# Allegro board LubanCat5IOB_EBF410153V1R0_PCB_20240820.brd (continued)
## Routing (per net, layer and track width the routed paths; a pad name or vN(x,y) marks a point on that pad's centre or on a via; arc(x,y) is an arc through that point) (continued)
PCIE30_PORT0_RX0P: length 157.5
  TOP w0.165: v2(71.42,16.88) 71.69,17.15 71.69,17.91 71.64,17.95 J2.20 ; v1(162.49,87.77) 162.19,88.07 162.19,92.81 162.29,92.91 J19.43
  BOTTOM w0.165: v2(71.42,16.88) 71.66,16.63 71.66,16.09 72.12,15.62 73.37,15.62 73.79,16.04 73.79,18.07 arc(73.93,18.78) 74.33,19.38 74.64,19.69 arc(75.21,20.07) 75.9,20.21 79.45,20.21 arc(79.51,20.21) 79.56,20.22 81.94,20.63 arc(81.99,20.63) 82.05,20.63 84.43,20.22 arc(84.48,20.21) 84.53,20.21 arc(84.59,20.21) 84.64,20.22 86.69,20.57 arc(86.9,20.59) 87.1,20.57 89.15,20.22 arc(89.21,20.21) 89.26,20.21 92.33,20.21 arc(93.22,20.58) 93.59,21.47 93.59,24.46 94.28,28.43 93.6,32.3 93.58,32.59 94.02,35.16 93.49,38.26 94.05,41.49 94.05,41.65 94.04,41.65 94.04,45.73 95.2,48.3 96.24,49.72 98.04,51.53 arc(98.77,52.01) 99.63,52.18 101.33,52.18 105.86,51.4 110.4,52.18 111.18,52.18 114.51,51.61 117.84,52.18 124.02,52.18 arc(124.99,52.38) 125.81,52.92 126.26,53.38 arc(126.99,53.87) 127.85,54.04 132.12,54.04 135.52,53.45 138.92,54.04 144.93,54.04 arc(145.75,54.2) 146.44,54.66 147.04,55.26 arc(147.38,55.77) 147.5,56.37 147.5,59.85 147.48,60.07 146.92,63.28 147.48,66.49 147.5,66.71 147.5,71.47 arc(147.84,73.18) 148.81,74.63 152.55,78.37 152.62,78.44 arc(152.95,78.94) 153.07,79.54 arc(153.18,80.1) 153.5,80.57 153.66,80.72 157.67,84.74 157.78,84.85 arc(158.48,85.32) 159.31,85.48 159.92,85.48 arc(160.64,85.63) 161.25,86.03 162.19,86.97 162.19,87.47 v1(162.49,87.77)
PCIE30_PORT0_RX1N: length 150.9
  TOP w0.165: v2(73,20.37) 72.76,20.13 72.76,19.78 72.84,19.7 J2.26 ; J19.29 158.79,92.91 158.9,92.81 158.9,90.83 arc(158.83,90.68) 158.68,90.62 arc(158.53,90.55) 158.47,90.4 158.47,90.17 arc(158.53,90.02) 158.68,89.95 arc(158.83,89.89) 158.9,89.74 158.9,89.51 arc(158.83,89.36) 158.68,89.29 arc(158.53,89.23) 158.47,89.08 158.47,88.85 arc(158.53,88.7) 158.68,88.63 arc(158.83,88.57) 158.9,88.42 158.9,88.07 v1(158.59,87.77)
  BOTTOM w0.165: v1(158.59,87.77) 158.9,88.07 158.9,88.51 arc(158.72,88.93) 158.3,89.11 156.87,89.11 arc(155.99,88.93) 155.25,88.44 154.97,88.15 150.69,83.87 arc(150.57,83.7) 150.53,83.5 150.53,79.91 arc(150.41,79.3) 150.06,78.78 146.99,75.71 146.99,75.7 arc(146.03,74.27) 145.69,72.58 145.69,71.68 arc(145.48,70.6) 144.86,69.68 144.1,68.92 arc(143.85,68.54) 143.76,68.1 143.76,67.44 144.27,66.93 144.27,62.91 arc(144.27,62.85) 144.26,62.8 143.79,60.11 arc(143.79,60.05) 143.79,59.99 143.8,59.99 143.8,59.08 143.79,59.07 143.79,57.12 arc(143.36,56.09) 142.33,55.66 138.78,55.66 135.52,55.1 132.26,55.66 122.72,55.66 arc(122.13,55.55) 121.64,55.21 121.29,54.87 arc(120.61,54.41) 119.8,54.25 114.68,54.25 arc(114.39,54.31) 114.15,54.47 arc(113.63,54.82) 113.01,54.94 109.68,54.94 105.56,54.23 102.1,54.83 99.27,54.83 arc(97.76,54.53) 96.48,53.67 94.46,51.65 93.7,50.36 93.17,49.6 92.52,47.77 92.11,46.29 92.11,42.02 92.08,41.39 91.52,38.15 92.03,35.21 91.56,32.51 92.18,28.93 91.95,27.58 91.85,26.37 arc(91.57,24.97) 90.78,23.78 89.38,22.39 arc(88.62,21.88) 87.72,21.7 86.3,21.7 arc(86.21,21.71) 86.11,21.7 84.44,21.41 arc(84.38,21.4) 84.33,21.4 arc(84.2,21.41) 84.07,21.42 81.92,21.8 arc(81.87,21.8) 81.81,21.8 79.66,21.42 arc(79.61,21.42) 79.55,21.42 79.25,21.42 arc(79.2,21.42) 79.14,21.42 76.82,21.83 arc(76.76,21.83) 76.71,21.83 74.38,21.42 arc(74.33,21.42) 74.28,21.42 72.96,21.42 72.76,21.21 72.76,20.62 v2(73,20.37)
PCIE30_PORT0_RX1P: length 150.8
  TOP w0.165: v2(72.23,20.37) 72.47,20.13 72.47,19.73 72.44,19.7 J2.24 ; v1(159.49,87.77) 159.19,88.07 159.19,92.81 159.29,92.91 J19.31
  BOTTOM w0.165: v1(159.49,87.77) 159.19,88.07 159.19,88.51 arc(158.93,89.14) 158.3,89.4 156.87,89.4 arc(155.88,89.2) 155.04,88.64 154.76,88.36 150.48,84.08 arc(150.3,83.82) 150.24,83.5 150.24,79.91 arc(150.14,79.41) 149.86,78.99 146.78,75.91 arc(145.76,74.38) 145.4,72.58 145.4,71.68 arc(145.21,70.71) 144.66,69.89 143.9,69.12 arc(143.58,68.65) 143.47,68.1 143.47,67.31 143.98,66.81 143.98,62.91 arc(143.98,62.88) 143.98,62.85 143.51,60.16 arc(143.5,60.05) 143.51,59.94 143.5,59.93 143.5,57.12 arc(143.16,56.3) 142.33,55.96 138.76,55.96 135.52,55.39 132.28,55.96 122.72,55.96 arc(122.02,55.82) 121.43,55.42 121.09,55.08 arc(120.5,54.68) 119.8,54.55 114.68,54.55 arc(114.5,54.58) 114.35,54.68 arc(113.74,55.09) 113.01,55.23 109.66,55.23 105.56,54.52 102.12,55.12 99.27,55.12 arc(97.65,54.8) 96.28,53.88 94.23,51.83 94.2,51.79 93.45,50.52 92.91,49.73 92.24,47.86 91.82,46.33 91.82,42.03 91.79,41.4 91.23,38.15 91.73,35.21 91.27,32.51 91.89,28.93 91.66,27.62 91.55,26.38 91.55,26.37 arc(91.3,25.08) 90.57,23.99 89.18,22.6 arc(88.51,22.15) 87.72,21.99 86.33,21.99 arc(86.2,22) 86.06,21.99 84.39,21.7 arc(84.36,21.7) 84.33,21.69 arc(84.23,21.7) 84.12,21.71 81.97,22.09 arc(81.87,22.09) 81.76,22.09 79.61,21.71 arc(79.58,21.71) 79.55,21.71 79.25,21.71 arc(79.22,21.71) 79.19,21.71 76.87,22.12 arc(76.76,22.12) 76.66,22.12 74.33,21.71 arc(74.31,21.71) 74.28,21.71 72.84,21.71 72.47,21.34 72.47,20.62 v2(72.23,20.37)
PCIE30_PORT0_TX0N: length 151.3
  TOP w0.165: J2.38 75.24,17.95 75.18,17.89 75.18,17.09 v2(75.4,16.88)
  BOTTOM w0.165: v2(75.4,16.88) 75.15,16.63 75.15,16.17 75.32,16 75.9,16 76.09,16.19 76.09,18.15 arc(76.4,18.91) 77.17,19.23 78.52,19.23 arc(78.62,19.27) 78.67,19.38 arc(78.71,19.48) 78.81,19.52 79.18,19.52 arc(79.29,19.48) 79.33,19.38 arc(79.37,19.27) 79.47,19.23 79.84,19.23 arc(79.95,19.27) 79.99,19.38 arc(80.03,19.48) 80.13,19.52 80.5,19.52 arc(80.61,19.48) 80.65,19.38 arc(80.69,19.27) 80.79,19.23 81.16,19.23 arc(81.27,19.27) 81.31,19.38 arc(81.35,19.48) 81.46,19.52 81.82,19.52 arc(81.93,19.48) 81.97,19.38 arc(82.01,19.27) 82.12,19.23 85,19.23 arc(85.03,19.23) 85.06,19.23 86.97,19.57 arc(87.08,19.58) 87.19,19.57 89.1,19.23 arc(89.13,19.23) 89.16,19.23 93.01,19.23 arc(93.83,19.57) 94.17,20.39 94.17,23.86 arc(94.17,23.92) 94.18,23.97 94.69,26.91 arc(94.84,28.67) 94.69,30.42 94.31,32.61 94.71,34.76 94.62,35.28 94.18,37.83 arc(94.17,37.88) 94.17,37.94 arc(94.17,37.99) 94.18,38.04 94.7,41.03 arc(94.7,41.09) 94.7,41.15 94.69,41.17 94.69,44.71 95.61,46.97 98.35,49.7 arc(99.4,50.4) 100.64,50.65 105.86,50.65 110.46,51.45 111.12,51.45 114.51,50.86 117.9,51.45 124.49,51.45 arc(125.58,51.67) 126.51,52.29 126.92,52.69 arc(127.77,53.27) 128.78,53.47 132.07,53.47 135.52,52.87 138.97,53.47 145.67,53.47 arc(146.24,53.58) 146.72,53.9 147.36,54.54 147.49,54.67 arc(147.88,55.26) 148.02,55.95 148.02,59.88 148,60.14 147.45,63.28 148,66.42 148.02,66.68 148.02,70.47 arc(148.42,72.51) 149.58,74.24 151.94,76.6 152.19,76.85 arc(153.06,77.43) 154.08,77.63 154.36,77.63 arc(155.14,77.79) 155.8,78.23 156.64,79.07 arc(157.41,79.59) 158.32,79.77 158.57,79.77 arc(159.01,79.86) 159.38,80.1 159.83,80.55 arc(159.98,80.78) 160.03,81.05 160.03,82.69 arc(160.22,83.63) 160.75,84.42 162.97,86.65 arc(163.31,87.15) 163.43,87.75 163.43,89.45 C177.1
PCIE30_PORT0_TX0P: length 151.3
  TOP w0.165: v2(74.62,16.88) 74.89,17.15 74.89,17.91 74.84,17.95 J2.36
  BOTTOM w0.165: C178.1 163.72,89.45 163.72,87.75 arc(163.58,87.04) 163.18,86.44 161.06,84.32 160.96,84.21 arc(160.49,83.52) 160.32,82.69 160.32,81.05 arc(160.25,80.67) 160.03,80.34 159.59,79.9 arc(159.12,79.59) 158.57,79.48 158.32,79.48 arc(157.52,79.32) 156.84,78.86 156,78.02 arc(155.25,77.52) 154.36,77.34 154.08,77.34 arc(153.17,77.16) 152.4,76.65 152.15,76.39 149.78,74.03 arc(148.69,72.4) 148.31,70.47 148.31,66.67 148.29,66.38 147.75,63.28 148.29,60.18 148.31,59.89 148.31,55.95 arc(148.15,55.14) 147.7,54.47 147.56,54.33 146.93,53.69 arc(146.35,53.31) 145.67,53.17 139,53.17 135.52,52.57 132.04,53.17 128.84,53.17 arc(127.89,52.98) 127.08,52.45 126.72,52.08 arc(125.69,51.4) 124.49,51.16 117.93,51.16 114.51,50.56 111.09,51.16 110.49,51.16 105.89,50.36 100.64,50.36 arc(99.51,50.13) 98.55,49.49 95.86,46.8 94.99,44.66 94.99,41.2 arc(95,41.09) 94.99,40.98 94.47,37.99 arc(94.46,37.97) 94.46,37.94 arc(94.46,37.91) 94.47,37.88 95.01,34.75 94.61,32.61 94.98,30.47 arc(95.13,28.67) 94.98,26.86 94.47,23.92 arc(94.46,23.89) 94.46,23.86 94.46,20.39 arc(94.04,19.36) 93.01,18.94 89.16,18.94 arc(89.1,18.94) 89.05,18.95 87.14,19.28 arc(87.08,19.28) 87.02,19.28 85.11,18.95 arc(85.06,18.94) 85,18.94 77.17,18.94 arc(76.61,18.71) 76.38,18.15 76.38,16.07 76.02,15.71 75.2,15.71 74.86,16.05 74.86,16.63 v2(74.62,16.88)
PCIE30_PORT0_TX1N: length 146.2
  TOP w0.165: J2.42 76.04,19.7 75.99,19.75 75.99,20.02 76.15,20.18 86.27,20.18 arc(86.37,20.14) 86.41,20.04 arc(86.45,19.94) 86.55,19.9 86.93,19.9 arc(87.03,19.94) 87.07,20.04 arc(87.11,20.14) 87.21,20.18 87.59,20.18 arc(87.69,20.14) 87.73,20.04 arc(87.77,19.94) 87.87,19.9 88.25,19.9 arc(88.35,19.94) 88.39,20.04 arc(88.43,20.14) 88.53,20.18 88.91,20.18 arc(89.01,20.14) 89.05,20.04 arc(89.09,19.94) 89.19,19.9 89.57,19.9 arc(89.67,19.94) 89.71,20.04 arc(89.75,20.14) 89.85,20.18 90.35,20.18 90.93,20.77 90.93,22.33 v1(91.2,22.6)
  BOTTOM w0.165: C175.1 160.38,89.45 160.38,87.57 arc(160.24,87.22) 159.88,87.07 158.12,87.07 arc(157.13,86.87) 156.3,86.32 152.46,82.48 arc(151.92,81.67) 151.73,80.71 151.73,80.18 arc(151.59,79.49) 151.2,78.91 147.65,75.35 arc(146.72,73.97) 146.39,72.33 146.39,66.72 arc(146.39,66.69) 146.39,66.66 145.82,63.39 arc(145.81,63.28) 145.82,63.17 146.39,59.9 arc(146.39,59.87) 146.39,59.84 146.39,57.34 arc(146.27,56.71) 145.91,56.18 145.32,55.59 arc(144.83,55.26) 144.25,55.14 138.83,55.14 135.52,54.57 132.21,55.14 126.88,55.14 arc(126.13,54.99) 125.49,54.56 125.03,54.11 arc(124.42,53.7) 123.69,53.55 113.85,53.55 arc(113.64,53.6) 113.47,53.71 arc(112.99,54.03) 112.43,54.14 110.89,54.14 arc(110.84,54.14) 110.78,54.13 106.7,53.42 arc(106.1,53.37) 105.51,53.42 102.52,53.94 arc(102.47,53.95) 102.42,53.95 100.2,53.95 arc(98.35,53.58) 96.79,52.54 94.58,50.33 93.65,48.93 92.76,45.86 92.76,41.64 92.22,38.49 92.74,35.5 92.22,32.55 92.95,28.37 92.37,25.01 92.37,21.8 91.94,21.38 91.3,21.38 90.93,21.74 90.93,22.33 v1(91.2,22.6)
PCIE30_PORT0_TX1P: length 146.2
  TOP w0.165: v1(90.38,22.6) 90.64,22.33 90.64,20.89 90.23,20.47 76.03,20.47 75.69,20.14 75.69,19.75 75.64,19.7 J2.40
  BOTTOM w0.165: v1(90.38,22.6) 90.64,22.33 90.64,21.62 91.18,21.08 92.06,21.08 92.66,21.68 92.66,24.99 93.25,28.37 92.52,32.55 93.03,35.5 92.51,38.49 93.06,41.61 93.06,45.81 93.92,48.81 94.81,50.14 97,52.33 arc(98.47,53.31) 100.2,53.66 102.42,53.66 arc(102.44,53.66) 102.47,53.65 105.46,53.14 arc(106.1,53.08) 106.75,53.14 110.83,53.85 arc(110.86,53.85) 110.89,53.85 112.43,53.85 arc(112.88,53.76) 113.26,53.51 arc(113.53,53.33) 113.85,53.26 123.69,53.26 arc(124.53,53.43) 125.23,53.9 125.69,54.36 arc(126.24,54.72) 126.88,54.85 132.19,54.85 135.52,54.27 138.85,54.85 144.25,54.85 arc(144.94,54.99) 145.52,55.38 146.12,55.97 arc(146.54,56.6) 146.69,57.34 146.69,59.84 arc(146.68,59.89) 146.68,59.95 146.11,63.22 arc(146.1,63.28) 146.11,63.34 146.68,66.61 arc(146.68,66.66) 146.69,66.72 146.69,72.33 arc(146.99,73.85) 147.85,75.15 151.41,78.7 arc(151.86,79.38) 152.02,80.18 152.02,80.71 arc(152.19,81.56) 152.67,82.27 156.51,86.11 arc(157.24,86.6) 158.12,86.78 159.88,86.78 arc(160.44,87.01) 160.67,87.57 160.67,89.45 C176.1
PCIE30_PORT1_REF_CLKN: length 52.1
  TOP w0.114: J2.55 78.84,22.26 78.76,22.34 78.76,23.06 78.35,23.47 78.35,23.79 arc(78.39,23.89) 78.49,23.94 arc(78.6,23.98) 78.64,24.08 78.64,24.25 arc(78.6,24.35) 78.49,24.39 arc(78.39,24.44) 78.35,24.54 78.35,24.71 arc(78.39,24.81) 78.49,24.85 arc(78.6,24.89) 78.64,25 78.64,25.16 arc(78.6,25.27) 78.49,25.31 arc(78.39,25.35) 78.35,25.46 78.35,25.62 arc(78.39,25.72) 78.49,25.77 arc(78.6,25.81) 78.64,25.91 78.64,26.08 arc(78.6,26.18) 78.49,26.22 arc(78.39,26.27) 78.35,26.37 78.35,27.37 77.99,27.72 77.99,30.9 78.5,31.41 78.5,45.87 79.08,46.46 94.44,46.46 98.27,50.29 100.88,50.29 101.08,50.09 R244.1 101.32,49.78 R243.2
PCIE30_PORT1_REF_CLKP: length 51.4
  TOP w0.114: J2.53 78.44,22.26 78.52,22.34 78.52,22.96 78.11,23.37 78.11,27.27 77.75,27.62 77.75,31 78.26,31.51 78.26,45.97 78.98,46.7 94.34,46.7 98.17,50.54 100.94,50.54 101.08,50.68 R245.1 101.35,50.8 R242.2
PCIE30_PORT1_RX0N: length 90.3
  TOP w0.165: J2.37 75.24,22.35 75.19,22.4 75.19,24.99 73.84,26.34 73.84,32.94 73.34,33.44 72.3,33.44 v1(72.04,33.7)
  ART03 w0.114: J20.A17 6.25,41.04 9.55,41.04 10.16,41.65 14.83,41.65 16.03,42.84 18.11,42.84 18.49,43.22 21.88,43.22 arc(21.91,43.22) 21.95,43.22 23.83,43.55 arc(23.87,43.55) 23.91,43.55 25.78,43.22 arc(25.82,43.22) 25.86,43.22 30.46,43.22 34.01,39.66 36.41,39.66 arc(36.43,39.66) 36.45,39.66 38.65,39.28 arc(38.89,39.26) 39.12,39.28 41.32,39.66 arc(41.34,39.66) 41.36,39.66 arc(41.38,39.66) 41.4,39.66 43.88,39.23 arc(43.96,39.22) 44.04,39.23 46.51,39.66 arc(46.53,39.66) 46.55,39.66 51.12,39.66 53.85,39.19 56.58,39.66 58.51,39.33 60.44,39.66 63.55,39.12 66.66,39.66 71.02,39.66 71.37,39.31 71.37,35.12 71.81,34.68 72.6,34.68 72.95,34.33 72.95,33.7 72.66,33.41 72.33,33.41 v1(72.04,33.7)
PCIE30_PORT1_RX0P: length 90.3
  TOP w0.165: J2.35 74.84,22.35 74.89,22.4 74.89,24.87 73.55,26.22 73.55,32.82 73.22,33.15 72.3,33.15 v1(72.04,32.89)
  ART03 w0.114: v1(72.04,32.89) 72.33,33.18 72.75,33.18 73.18,33.61 73.18,34.43 72.69,34.91 71.91,34.91 71.61,35.22 71.61,39.41 71.12,39.9 66.64,39.9 63.55,39.36 60.44,39.9 58.51,39.56 56.58,39.9 53.85,39.42 51.14,39.9 46.55,39.9 arc(46.51,39.89) 46.47,39.89 44,39.46 arc(43.96,39.46) 43.92,39.46 41.44,39.89 arc(41.4,39.89) 41.36,39.9 arc(41.32,39.89) 41.28,39.89 39.08,39.51 arc(38.89,39.49) 38.69,39.51 36.49,39.89 arc(36.45,39.89) 36.41,39.9 34.11,39.9 30.55,43.45 25.86,43.45 arc(25.84,43.45) 25.82,43.45 23.95,43.78 arc(23.87,43.78) 23.79,43.78 21.91,43.45 arc(21.89,43.45) 21.88,43.45 18.39,43.45 18.01,43.07 15.93,43.07 14.74,41.88 10.06,41.88 9.45,41.27 7.8,41.27 7.57,41.5 7.57,41.92 7.8,42.15 J20.A16
PCIE30_PORT1_RX1N: length 92.6
  TOP w0.165: J2.41 76.04,22.35 75.99,22.4 75.99,25.61 74.79,26.81 74.79,34.37 74.24,34.91 67.85,34.91 v1(67.59,35.18)
  ART03 w0.114: v1(67.59,35.18) 67.88,34.88 68.21,34.88 68.44,35.11 68.44,37.17 67.87,37.73 66.84,37.73 arc(66.82,37.73) 66.8,37.73 63.81,37.21 arc(63.73,37.2) 63.65,37.21 60.66,37.73 arc(60.64,37.73) 60.62,37.73 60.48,37.73 arc(60.47,37.73) 60.45,37.73 58.52,37.4 arc(58.44,37.39) 58.36,37.4 56.43,37.73 arc(56.41,37.73) 56.39,37.73 arc(56.37,37.73) 56.35,37.73 53.74,37.28 arc(53.66,37.27) 53.58,37.28 50.97,37.73 arc(50.95,37.73) 50.93,37.73 arc(50.91,37.73) 50.89,37.73 48.79,37.37 arc(48.71,37.36) 48.63,37.37 46.53,37.73 arc(46.51,37.73) 46.49,37.73 arc(46.47,37.73) 46.45,37.73 44.09,37.32 arc(44.01,37.31) 43.93,37.32 41.57,37.73 arc(41.55,37.73) 41.53,37.73 arc(41.51,37.73) 41.49,37.73 39.07,37.31 arc(38.99,37.3) 38.91,37.31 36.49,37.73 arc(36.47,37.73) 36.45,37.73 32.97,37.73 29.52,41.19 26.05,41.19 arc(26.01,41.19) 25.98,41.19 23.91,41.55 arc(23.88,41.55) 23.84,41.55 21.78,41.19 arc(21.74,41.19) 21.7,41.19 16.71,41.19 15.62,40.09 14.12,40.09 13.92,39.89 13.92,37.18 13.56,36.82 9.35,36.82 8.91,37.25 7.55,37.25 7.32,37.02 7.32,36.38 7.55,36.15 J20.A22
PCIE30_PORT1_RX1P: length 92.5
  TOP w0.165: J2.39 75.64,22.35 75.69,22.4 75.69,25.49 74.5,26.68 74.5,34.25 74.12,34.62 67.85,34.62 v1(67.59,34.36)
  ART03 w0.114: v1(67.59,34.36) 67.88,34.65 68.3,34.65 68.67,35.02 68.67,37.27 67.97,37.97 66.84,37.97 arc(66.8,37.96) 66.76,37.96 63.77,37.44 arc(63.73,37.44) 63.69,37.44 60.7,37.96 arc(60.66,37.96) 60.62,37.97 60.48,37.97 arc(60.45,37.96) 60.41,37.96 58.48,37.62 arc(58.44,37.62) 58.4,37.62 56.47,37.96 arc(56.43,37.96) 56.39,37.97 arc(56.35,37.96) 56.31,37.96 53.7,37.5 arc(53.66,37.5) 53.62,37.5 51.01,37.96 arc(50.97,37.96) 50.93,37.97 arc(50.89,37.96) 50.85,37.96 48.75,37.59 arc(48.71,37.59) 48.67,37.59 46.57,37.96 arc(46.53,37.96) 46.49,37.97 arc(46.45,37.96) 46.41,37.96 44.05,37.55 arc(44.01,37.55) 43.97,37.55 41.61,37.96 arc(41.57,37.96) 41.53,37.97 arc(41.49,37.96) 41.45,37.96 39.03,37.54 arc(38.99,37.53) 38.95,37.54 36.53,37.96 arc(36.49,37.96) 36.45,37.97 33.07,37.97 29.62,41.42 26.05,41.42 arc(26.03,41.42) 26.01,41.42 23.95,41.78 arc(23.88,41.78) 23.8,41.78 21.74,41.42 arc(21.72,41.42) 21.7,41.42 16.61,41.42 15.52,40.32 14.03,40.32 13.69,39.99 13.69,37.28 13.46,37.05 9.45,37.05 9.01,37.48 6.47,37.48 J20.A21
PCIE30_PORT1_TX0N: length 89.5
  TOP w0.165: C190.1 v1(12.32,42.54) ; v1(73.99,37.21) 74.25,36.95 75.22,36.95 75.83,36.33 75.83,27.11 76.79,26.16 76.79,22.4 76.84,22.35 J2.45
  ART03 w0.114: v1(73.99,37.21) 73.7,36.92 73.03,36.92 72.8,37.14 72.8,40.17 72.16,40.81 66.56,40.81 63.47,40.27 60.36,40.81 58.51,40.49 56.66,40.81 53.93,40.34 51.22,40.81 46.43,40.81 43.96,40.38 41.46,40.81 38.98,40.38 36.53,40.81 34.77,40.81 31.11,44.46 25.85,44.46 arc(25.83,44.47) 25.81,44.47 23.97,44.79 arc(23.89,44.8) 23.81,44.79 21.97,44.47 arc(21.95,44.47) 21.93,44.46 18.19,44.46 17.76,44.04 13.23,44.04 12.95,44.32 11.33,44.32 10.97,43.95 10.97,43.3 11.33,42.94 11.93,42.94 v1(12.32,42.54)
PCIE30_PORT1_TX0P: length 88.2
  TOP w0.165: v1(73.99,36.39) 74.25,36.65 75.1,36.65 75.54,36.21 75.54,26.99 76.49,26.04 76.49,22.4 76.44,22.35 J2.43 ; C189.1 v1(12.32,43.56)
  ART03 w0.114: v1(73.99,36.39) 73.7,36.68 72.93,36.68 72.57,37.05 72.57,40.08 72.06,40.58 66.58,40.58 63.47,40.04 60.36,40.58 58.51,40.26 56.66,40.58 53.93,40.1 51.2,40.58 46.45,40.58 43.96,40.15 41.46,40.58 38.98,40.15 36.51,40.58 34.67,40.58 31.02,44.23 25.85,44.23 arc(25.81,44.24) 25.77,44.24 23.93,44.56 arc(23.89,44.56) 23.85,44.56 22,44.24 arc(21.97,44.24) 21.93,44.23 18.29,44.23 17.86,43.8 13.13,43.8 12.85,44.08 11.43,44.08 11.2,43.86 11.2,43.4 11.43,43.17 11.93,43.17 v1(12.32,43.56)
PCIE30_PORT1_TX1N: length 90.1
  TOP w0.165: v1(69.88,38.51) 70.14,38.24 76.25,38.24 77.06,37.43 77.06,27.35 77.59,26.83 77.59,22.4 77.64,22.35 J2.49 ; C192.1 v1(12.32,38.48)
  ART03 w0.114: v1(12.32,38.48) 11.93,38.87 11.16,38.87 10.79,39.24 10.79,40.73 11.23,41.16 15.14,41.16 16.16,42.18 18.52,42.18 18.78,42.44 21.9,42.44 arc(21.92,42.44) 21.94,42.44 23.87,42.77 arc(23.94,42.78) 24.02,42.77 25.95,42.44 arc(25.97,42.44) 25.99,42.44 30.17,42.44 33.75,38.85 36.57,38.85 38.99,38.43 41.3,38.83 43.87,38.39 46.58,38.86 48.81,38.47 51.03,38.86 53.76,38.38 56.49,38.86 58.51,38.51 60.53,38.86 63.64,38.32 66.73,38.85 68.53,38.85 69.14,38.24 69.61,38.24 v1(69.88,38.51)
PCIE30_PORT1_TX1P: length 88.8
  TOP w0.165: C191.1 v1(12.32,39.5) ; v1(69.88,37.69) 70.14,37.95 76.13,37.95 76.77,37.31 76.77,27.23 77.29,26.71 77.29,22.4 77.24,22.35 J2.47
  ART03 w0.114: v1(12.32,39.5) 11.93,39.1 11.25,39.1 11.03,39.33 11.03,40.64 11.32,40.93 15.24,40.93 16.25,41.95 18.62,41.95 18.87,42.2 21.9,42.2 arc(21.94,42.21) 21.98,42.21 23.91,42.55 arc(23.94,42.55) 23.98,42.55 25.91,42.21 arc(25.95,42.21) 25.99,42.2 30.07,42.2 33.66,38.62 36.55,38.62 38.99,38.2 41.3,38.6 43.87,38.15 46.58,38.62 48.81,38.24 51.03,38.62 53.76,38.15 56.49,38.62 58.51,38.27 60.53,38.62 63.64,38.08 66.75,38.62 68.43,38.62 69.04,38.01 69.55,38.01 v1(69.88,37.69)
PCIE30X1_0_CLKREQN_M0: length 110.3
  TOP w0.152: v2(80.04,17.69) J2.62 ; v1(125.85,57.21) 125.4,56.75 125.4,49.7 124.92,49.21 123.48,49.21 123.15,48.88 123.15,42.78 122.6,42.24 109.91,42.24 109.6,41.93 109.6,37.32 109.02,36.74 97.59,36.74 97.28,36.44 97.28,28.39 96.87,27.97 v1(89.92,27.97)
  ART03 w0.152: v1(89.92,27.97) 88.6,26.66 80.87,26.66 v2(80.67,26.86)
  ART04 w0.152: v1(125.85,57.21) 126.29,56.77 130.24,56.77 130.56,57.09 130.56,58.39 129.95,59 129.95,67.61 130.48,68.15 130.48,74.15 v1(130.1,74.54) ; v2(80.04,17.69) 80.04,18.69 80.67,19.32 v2(80.67,26.86)
  BOTTOM w0.152: R145.1 129.68,77.33 130.1,76.91 v1(130.1,74.54)
PCIE30X1_0_PERSTN_M0: length 126
  TOP w0.152: v2(80.04,16.85) 80.44,17.25 J2.64
  ART03 w0.152: v1(129.29,59.28) 134.34,59.28 134.65,58.98 134.65,56.81 134.95,56.5 144.58,56.5 144.89,56.2 144.89,39.18 143.26,37.55 143.26,30.9 140.23,27.88 103.81,27.88 100.3,31.38 88.9,31.38 87.54,30.02 81.49,30.02 v2(81.18,29.71)
  ART04 w0.152: v2(81.18,29.71) 81.18,18.79 80.46,18.07 80.46,17.27 v2(80.04,16.85)
  BOTTOM w0.152: R144.2 v1(129.29,59.28)
PCIE30X1_0_WAKEN_M0: length 122.7
  TOP w0.152: J2.60 79.64,17.25 v2(79.24,16.85) ; v1(124.85,57.21) 124.85,50.19 124.64,49.98 123.14,49.98 122.64,49.48 122.64,43.05 122.33,42.75 109.7,42.75 109.09,42.14 109.09,37.56 108.79,37.25 97.38,37.25 96.77,36.65 96.77,29.22 96.52,28.97 v1(89.92,28.97)
  ART03 w0.152: v1(89.92,28.97) 88.81,27.86 80.1,27.86 v2(79.63,28.34)
  ART04 w0.152: v2(79.63,28.34) 79.63,27.42 80.06,26.99 80.06,19.62 79.62,19.18 79.62,17.23 v2(79.24,16.85) ; v1(124.85,57.21) 125.8,56.25 132.05,56.25 132.51,56.72 132.51,59.43 132.1,59.85 v1(132.1,74.54)
  BOTTOM w0.152: R148.1 127,78.1 127.64,78.74 131.19,78.74 131.83,78.1 131.83,74.81 v1(132.1,74.54)
PCIE30X1_1_CLKREQN_M1: length 149.2
  TOP w0.152: J3.12 v2(44.47,67.76) ; v1(129.92,57.28) 135.11,57.28 136.02,58.18 136.02,74.17 137.3,75.45 141.1,75.45 141.35,75.71 141.35,77.6 141.56,77.81 142.83,77.81 v1(143,77.98)
  ART03 w0.152: v1(47.29,49.26) 74.39,49.26 74.7,49.57 74.7,50.51 75.01,50.81 78.38,50.81 79.15,51.58 81.15,51.58 81.51,51.22 82.04,51.22 82.45,50.81 83.24,50.81 84.35,51.93 128.32,51.93 128.65,52.26 128.65,56.01 v1(129.92,57.28)
  ART04 w0.152: v1(47.29,49.26) 47.75,48.8 47.75,48.1 47.42,47.77 46.84,47.77 46.35,47.28 44.5,47.28 43.87,47.92 43.87,64.78 44.88,65.8 44.88,67.35 v2(44.47,67.76)
  BOTTOM w0.152: R266.1 v1(143,77.98)
PCIE30X1_1_PERSTN_M1: length 118.9
  TOP w0.152: R268.2 v1(133.1,58.55) ; J3.16 v2(45.27,67.76)
  ART03 w0.152: v1(46.29,48.26) 46.74,48.71 74.96,48.71 75.26,49.01 75.26,49.8 75.77,50.31 78.77,50.31 79.13,50.67 81.83,50.67 82.32,50.18 83.54,50.18 84.3,50.94 128.35,50.94 129.46,52.06 132.77,52.06 133.1,52.39 v1(133.1,58.55)
  ART04 w0.152: v2(45.27,67.76) 45.65,67.38 45.65,65.3 45.08,64.73 45.08,61.76 44.86,61.54 44.86,48.08 45.12,47.83 45.86,47.83 v1(46.29,48.26)
PCIE30X1_1_WAKEN_M1: length 165.5
  TOP w0.152: v2(44.47,66.92) 44.87,67.32 J3.14 ; v1(81.23,98.18) 81.74,98.68 81.74,100.47 82.07,100.8 101.02,100.8 101.04,100.79 118.66,100.79 120.02,99.43 126.52,99.43 126.92,99.84 131.04,99.84 132.41,98.47 145.52,98.47 146.05,97.93 148.35,97.93 v1(148.72,97.56)
  ART03 w0.152: v1(81.23,98.18) 81.23,96.07 80.75,95.59 80.75,89.5 80.44,89.19 44.17,89.19 43.87,88.89 43.87,84.74 v1(43.4,84.28)
  ART04 w0.152: v1(43.4,84.28) 41.78,82.66 41.78,80.12 41.4,79.74 41.4,70.75 43.96,68.19 43.96,67.43 v2(44.47,66.92)
  BOTTOM w0.152: R265.1 145.54,77.95 148.31,80.72 148.31,85.61 149.38,86.68 149.38,96.9 v1(148.72,97.56)
PCIE30X2_CLKREQN_M1: length 53.2
  TOP w0.152: v1(10.58,48.4) 10.79,48.18 R248.1 ; v1(30.91,60.42) 30.91,62.24 31.45,62.78 34.92,62.78 35.43,63.29 35.43,65.8 36.3,66.66 41,66.66 41.43,67.1 42.19,67.1 42.87,67.78 J3.4
  BOTTOM w0.152: v1(30.91,60.42) 30.38,59.89 10.55,59.89 10.03,59.37 10.03,54.23 10.72,53.54 10.72,48.54 v1(10.58,48.4)
PCIE30X2_PERSTN_M1: length 72.2
  TOP w0.152: J3.8 43.67,67.44 42.54,66.32 42.02,66.32 41.55,65.85 36.93,65.85 36.65,65.57 36.65,62.37 36.2,61.91 32.59,61.91 32.16,61.48 32.16,55.13 30.86,53.84 v1(30.86,43.83)
  BOTTOM w0.152: J20.A11 7.09,48.2 7.09,39.47 7.5,39.05 14.68,39.05 16.34,40.72 24.11,40.72 24.46,41.06 24.46,42.04 24.71,42.29 29.03,42.29 29.31,42.57 29.31,43.47 29.62,43.78 30.81,43.78 v1(30.86,43.83)
PCIE30X2_PRSNTN: length 119.3
  TOP w0.152: v1(11.58,46.12) 11.58,44.48 11.94,44.12 12.5,44.12 12.92,43.7 12.92,40.87 12.57,40.52 R137.1 ; J4.66 80.84,66.32 v2(80.44,65.92)
  ART03 w0.152: v1(74.82,51.32) 74.27,51.32 73.99,51.04 73.99,50.1 73.69,49.8 46.1,49.8 45.8,49.49 45.8,47.67 45.49,47.36 38.18,47.36 36.65,48.88 31.11,48.88 29.84,50.15 25.91,50.15 25.55,49.8 12.83,49.8 11.76,50.87 11.76,53.58 11.46,53.89 9.3,53.89 8.99,53.58 8.99,46.42 9.3,46.12 v1(11.58,46.12)
  ART04 w0.152: v2(80.44,65.92) 79.57,65.92 79.26,65.61 79.26,49.81 77.57,48.12 75.21,48.12 74.82,48.51 v1(74.82,51.32)
PCIE30X2_WAKEN_M1: length 50.1
  TOP w0.152: J3.6 43.27,67.61 42.33,66.67 41.84,66.67 41.4,66.23 36.7,66.23 36.07,65.6 36.07,63.01 35.41,62.35 31.88,62.35 31.55,62.02 v1(31.55,55.49) ; v1(10.78,55.12) 10.79,55.1 R247.1
  BOTTOM w0.152: v1(10.78,55.12) 12.33,53.56 23.84,53.56 24.14,53.85 31.28,53.85 31.55,54.12 v1(31.55,55.49)
PCIE30X4_CLKREQN_M1: length 173.8
  TOP w0.152: J19.52 164.53,86.47 164.53,87.56 164.74,87.77 165.94,87.77 166.24,88.08 166.24,92.2 166.47,92.43 166.47,94.79 166.12,95.15 149.83,95.15 149.35,95.63 149.35,98.46 148.93,98.88 146.48,98.88 145.8,99.57 132.36,99.57 131.52,100.41 120.4,100.41 119.14,101.66 81.58,101.66 81.23,101.31 v1(81.23,99.18) ; J3.20 v2(46.07,67.76)
  ART03 w0.152: v1(43.4,85.28) 43.21,85.48 43.21,89.37 43.54,89.7 79.93,89.7 80.24,90.01 80.24,95.8 80.72,96.28 80.72,98.67 v1(81.23,99.18)
  ART04 w0.152: v2(46.07,67.76) 45.67,68.16 44.96,68.16 42.55,70.58 42.55,82.56 43.89,83.91 43.89,84.79 v1(43.4,85.28)
PCIE30X4_PERSTN_M1: length 172.4
  TOP w0.152: J19.50 164.04,84.8 v1(163.54,84.3) ; J3.24 v2(46.87,67.76)
  ART03 w0.152: v1(44.4,85.28) 44.4,88.03 45.09,88.71 80.85,88.71 81.15,89.02 81.15,95.09 81.76,95.7 81.76,99.05 82.35,99.63 97.13,99.63 98.45,98.31 107.16,98.31 107.9,97.58 112.32,97.58 112.83,97.07 112.83,88 113.41,87.42 122.83,87.42 123.39,86.86 164.29,86.86 165.3,85.84 165.3,84.22 164.83,83.74 164.1,83.74 v1(163.54,84.3)
  ART04 w0.152: v1(44.4,85.28) 45.01,84.67 45.01,82.82 43.46,81.27 43.46,71.21 45.57,69.1 46.62,69.1 46.87,68.85 v2(46.87,67.76)
PCIE30X4_WAKEN_M1: length 166.9
  TOP w0.152: J19.54 165.04,85.33 v1(164.57,84.85) ; v2(46.07,66.92) 46.47,67.32 J3.22
  ART03 w0.152: v1(44.4,84.28) 45.01,84.89 45.01,86.3 45.34,86.63 76.02,86.63 77.67,88.28 81.28,88.28 81.61,88.61 81.61,94.55 82.27,95.21 82.27,97.96 82.97,98.66 96.89,98.66 97.69,97.86 106.86,97.86 107.57,97.14 111.81,97.14 112.24,96.71 112.24,87.34 112.6,86.98 122.48,86.98 123.14,86.33 134.83,86.33 135.69,85.46 163.96,85.46 v1(164.57,84.85)
  ART04 w0.152: v1(44.4,84.28) 44.4,83.76 44.4,83.76 44.4,83.7 43.92,83.22 43.92,82.51 43.05,81.65 43.05,70.83 45.19,68.7 46.15,68.7 46.48,68.37 46.48,67.33 v2(46.07,66.92)
PCIEX4_PETN0: length 8.3
  TOP w0.165: J20.B15 3.53,43.26 3.53,43.78 3.7,43.94 6.73,43.94 7.6,43.07 8.33,43.07 8.49,42.91 10.19,42.91 C190.2
PCIEX4_PETN1: length 9.6
  TOP w0.165: J20.B20 1.73,38.06 6.68,38.06 7.69,39.07 8.93,39.07 9.16,38.84 10.19,38.84 C192.2
PCIEX4_PETP0: length 9.5
  TOP w0.165: J20.B14 1.72,44.23 6.85,44.23 7.72,43.36 8.45,43.36 8.62,43.2 10.19,43.2 C189.2
PCIEX4_PETP1: length 10.9
  TOP w0.165: J20.B19 3.38,39.41 2.65,39.41 2.48,39.25 2.48,38.51 2.65,38.35 6.56,38.35 7.57,39.36 9.05,39.36 9.28,39.13 10.19,39.13 C191.2
PCIEX4_PRSNTN: length 23.4
  TOP w0.152: J20.B17 4.43,41.94 6.83,41.94 7.41,41.36 9.23,41.36 9.39,41.52 R328.2 R137.2
  BOTTOM w0.173: J20.B17 4.7,40.09 4.7,28.21 J20.B31
PCIEX4_PWR_EN: length 62.3
  TOP w0.152: J1.53 52.87,29.29 52.32,29.83 45.09,29.83 44.58,30.34 44.58,34.91 44.35,35.14 30.33,35.14 30.02,35.45 30.02,41.98 29.72,42.28 16.73,42.28 v1(15.58,43.43) 15.29,43.15 15.29,42.08 15.06,41.85 14.17,41.85 13.98,41.65 R256.1
  BOTTOM w0.152: v1(15.58,43.43) 15.88,43.74 R251.2
PCIEX4_REF_CLKN: length 104.4
  TOP w0.114: v1(102.12,48.64) 101.67,48.64 101.28,48.25 98.67,48.25 98.21,47.79 98.21,44.34 97.98,44.11 96.11,44.11 v1(95.86,44.36)
  ART03 w0.102: v1(95.86,44.36) 95.61,44.11 95.27,44.11 arc(95.22,44.11) 95.18,44.1 93.89,43.88 arc(93.85,43.87) 93.82,43.88 92.52,44.1 arc(92.48,44.11) 92.44,44.11 92.25,44.11 arc(92.21,44.11) 92.16,44.1 90.38,43.79 arc(90.35,43.79) 90.31,43.79 88.53,44.1 arc(88.49,44.11) 88.45,44.11 88,44.11 arc(87.96,44.11) 87.92,44.1 86.1,43.79 arc(86.07,43.78) 86.03,43.79 84.22,44.1 arc(84.17,44.11) 84.13,44.11 78.87,44.11 arc(78.82,44.11) 78.78,44.1 77.32,43.85 arc(77.28,43.84) 77.25,43.85 75.78,44.1 arc(75.74,44.11) 75.7,44.11 75.2,44.11 arc(75.16,44.11) 75.12,44.1 73.29,43.78 arc(73.25,43.78) 73.22,43.78 71.39,44.1 arc(71.35,44.11) 71.31,44.11 71.06,44.11 arc(71.02,44.11) 70.98,44.1 69.28,43.81 arc(69.24,43.8) 69.21,43.81 67.5,44.1 arc(67.46,44.11) 67.42,44.11 65.64,44.11 arc(65.6,44.11) 65.56,44.1 63.29,43.71 arc(63.25,43.7) 63.22,43.71 60.95,44.1 arc(60.91,44.11) 60.87,44.11 arc(60.82,44.11) 60.78,44.1 58.66,43.73 arc(58.4,43.71) 58.14,43.73 56.02,44.1 arc(55.88,44.12) 55.73,44.13 arc(55.69,44.13) 55.65,44.12 54.06,43.84 arc(53.97,43.84) 53.88,43.84 52.39,44.1 arc(52.35,44.11) 52.31,44.11 51.9,44.11 arc(51.86,44.11) 51.81,44.1 49.85,43.76 arc(49.82,43.76) 49.78,43.76 47.82,44.1 arc(47.78,44.11) 47.73,44.11 47.52,44.11 arc(47.47,44.11) 47.43,44.1 45.46,43.76 arc(45.43,43.76) 45.39,43.76 43.42,44.1 arc(43.38,44.11) 43.34,44.11 43.09,44.11 arc(43.05,44.11) 43.01,44.1 41.03,43.76 arc(40.99,43.76) 40.96,43.76 38.98,44.1 arc(38.94,44.11) 38.9,44.11 36.23,44.11 34.99,45.35 34.61,45.35 arc(34.59,45.35) 34.57,45.36 32.59,45.7 arc(32.51,45.71) 32.43,45.7 30.45,45.36 arc(30.43,45.35) 30.41,45.35 25.89,45.35 arc(25.87,45.35) 25.85,45.36 23.89,45.7 arc(23.81,45.71) 23.72,45.7 21.76,45.36 arc(21.74,45.35) 21.72,45.35 21.54,45.35 arc(21.52,45.35) 21.5,45.36 20.1,45.6 arc(20.02,45.61) 19.94,45.6 18.53,45.36 arc(18.52,45.35) 18.5,45.35 18.31,45.35 arc(18.3,45.35) 18.28,45.36 16.63,45.64 arc(16.55,45.65) 16.47,45.64 14.83,45.36 arc(14.81,45.35) 14.79,45.35 10.17,45.35 9.5,44.68 9.5,43.53 9.3,43.32 7.47,43.32 7.06,43.73 7.06,44.46 7.26,44.67 7.62,44.67 J20.A14
PCIEX4_REF_CLKP: length 104.4
  TOP w0.114: v1(102.12,47.62) 101.67,47.62 101.28,48.01 98.77,48.01 98.45,47.69 98.45,44.24 98.08,43.87 96.18,43.87 v1(95.86,43.55)
  ART03 w0.102: J20.A13 6.78,44.51 6.78,43.61 7.35,43.04 9.41,43.04 9.78,43.41 9.78,44.57 10.29,45.07 14.79,45.07 arc(14.83,45.08) 14.87,45.08 16.52,45.37 arc(16.55,45.37) 16.59,45.37 18.23,45.08 arc(18.27,45.08) 18.31,45.07 18.5,45.07 arc(18.54,45.08) 18.58,45.08 19.98,45.33 arc(20.02,45.33) 20.05,45.33 21.46,45.08 arc(21.5,45.08) 21.54,45.07 21.72,45.07 arc(21.77,45.08) 21.81,45.08 23.77,45.42 arc(23.81,45.43) 23.84,45.42 25.81,45.08 arc(25.85,45.08) 25.89,45.07 30.41,45.07 arc(30.45,45.08) 30.49,45.08 32.48,45.43 arc(32.51,45.43) 32.55,45.43 34.53,45.08 arc(34.57,45.08) 34.61,45.07 34.87,45.07 36.12,43.83 38.9,43.83 arc(38.91,43.83) 38.93,43.83 40.91,43.48 arc(40.99,43.48) 41.08,43.48 43.06,43.83 arc(43.08,43.83) 43.09,43.83 43.34,43.83 arc(43.36,43.83) 43.38,43.83 45.35,43.48 arc(45.43,43.48) 45.51,43.48 47.48,43.83 arc(47.5,43.83) 47.52,43.83 47.73,43.83 arc(47.75,43.83) 47.77,43.83 49.73,43.49 arc(49.82,43.48) 49.9,43.49 51.86,43.83 arc(51.88,43.83) 51.9,43.83 52.31,43.83 arc(52.32,43.83) 52.34,43.83 53.83,43.57 arc(53.97,43.56) 54.1,43.57 55.7,43.84 arc(55.72,43.85) 55.73,43.85 arc(55.85,43.84) 55.97,43.83 58.09,43.46 arc(58.4,43.43) 58.71,43.46 60.83,43.83 arc(60.85,43.83) 60.87,43.83 arc(60.88,43.83) 60.9,43.83 63.17,43.43 arc(63.25,43.43) 63.34,43.43 65.61,43.83 arc(65.63,43.83) 65.64,43.83 67.42,43.83 arc(67.44,43.83) 67.45,43.83 69.16,43.53 arc(69.24,43.52) 69.32,43.53 71.03,43.83 arc(71.04,43.83) 71.06,43.83 71.31,43.83 arc(71.32,43.83) 71.34,43.83 73.17,43.51 arc(73.25,43.5) 73.34,43.51 75.17,43.83 arc(75.18,43.83) 75.2,43.83 75.7,43.83 arc(75.72,43.83) 75.73,43.83 77.2,43.57 arc(77.28,43.57) 77.37,43.57 78.83,43.83 arc(78.85,43.83) 78.87,43.83 84.13,43.83 arc(84.15,43.83) 84.17,43.83 85.98,43.51 arc(86.07,43.5) 86.15,43.51 87.96,43.83 arc(87.98,43.83) 88,43.83 88.45,43.83 arc(88.47,43.83) 88.49,43.83 90.27,43.52 arc(90.35,43.51) 90.43,43.52 92.21,43.83 arc(92.23,43.83) 92.25,43.83 92.44,43.83 arc(92.46,43.83) 92.47,43.83 93.77,43.6 arc(93.85,43.59) 93.93,43.6 95.23,43.83 arc(95.25,43.83) 95.27,43.83 95.57,43.83 v1(95.86,43.55)
PDN: length 2.2
  TOP w0.152: v1(115.44,47.73) U26.7
  BOTTOM w0.152: v1(115.44,47.73) 115.16,48.01 R224.2
PE_TXN: length 20.4
  TOP w0.165: J23.31 129.3,70.92 129.05,70.67 129.05,68.71 128.27,67.93 122.33,67.93 120.88,66.49 119.63,66.49 119.02,65.87 119.02,60.68 C214.2
PE_TXP: length 20.4
  TOP w0.165: J23.33 128.5,70.92 128.75,70.67 128.75,68.83 128.15,68.23 122.21,68.23 120.76,66.78 119.51,66.78 118.73,65.99 118.73,60.68 C215.2
PETN0: length 3.5
  TOP w0.165: v1(163.09,91.85) 163.4,92.15 163.4,92.81 163.29,92.91 J19.47
  BOTTOM w0.165: C177.2 163.37,91.11 163.37,91.58 v1(163.09,91.85)
PETN1: length 3.5
  TOP w0.165: v1(160.09,91.85) 160.4,92.15 160.4,92.81 160.29,92.91 J19.35
  BOTTOM w0.165: v1(160.09,91.85) 160.34,91.6 160.34,91.14 C175.2
PETP0: length 3.5
  TOP w0.165: J19.49 163.79,92.91 163.69,92.81 163.69,92.15 v1(163.99,91.85)
  BOTTOM w0.165: v1(163.99,91.85) 163.75,91.61 163.75,91.15 C178.2
PETP1: length 3.5
  TOP w0.165: J19.37 160.79,92.91 160.69,92.81 160.69,92.15 v1(160.99,91.85)
  BOTTOM w0.165: C176.2 160.73,91.12 160.73,91.59 v1(160.99,91.85)
PHY0_CLKOUT125: length 2.7
  TOP w0.173: U4.35 74.5,77.67 v1(74.72,77.45)
  BOTTOM w0.173: v1(74.72,77.45) 74.94,77.22 R37.2
PHY0_LED1: length 40.8
  TOP w0.152: R44.1 74.9,75.84 v1(74.72,75.67) 74.3,76.09 74.3,76.47 73.9,76.87 U4.33
  ART04 w0.203: v1(74.72,75.67) 74.17,76.21 68.71,76.21 68.02,76.9 63.96,76.9 63.5,77.36 62.18,77.36 61.67,77.87 61.67,89.07 61.9,89.3 61.9,98.49 62.41,99 J6.14
PHY0_LED2: length 33.4
  TOP w0.152: v1(74.72,76.56) 74.72,76.83 74.29,77.27 U4.34
  BOTTOM w0.152: v1(74.72,76.56) 74.29,76.99 74.29,78.36 R43.1 76.08,78.88 77.04,78.88 77.34,79.19 77.34,81.96 77.04,82.26 77.04,83.53 77.98,84.47 77.98,88.41 78.49,88.91 80.39,88.91 80.77,89.3 80.77,96.36 80.47,96.66 77.98,96.66 77.75,96.89 J6.11
PHY1_CLKOUT125: length 2.9
  TOP w0.173: v1(56.32,77.45) 56.1,77.67 U3.35
  BOTTOM w0.173: v1(56.32,77.45) 56.54,77.22 R67.2
PHY1_LED1: length 43.8
  TOP w0.152: U3.33 55.67,76.87 55.89,76.65 55.89,75.84 56.34,75.4 v1(56.34,75.29) 56.89,75.84 R72.1
  ART04 w0.203: v1(56.34,75.29) 55.52,76.1 55.52,77.74 56.03,78.25 58.29,78.25 59.94,79.9 59.94,88.18 59.08,89.04 56.18,89.04 55.68,89.55 55.68,97.35 55.17,97.86 47.24,97.86 J7.14
PHY1_LED2: length 33.6
  TOP w0.152: U3.34 55.84,77.27 56.32,76.79 v1(56.32,76.45)
  ART04 w0.203: v1(56.32,76.45) 59.34,76.45 60.53,77.64 60.53,89.17 60.02,89.68 56.85,89.68 56.34,90.18 56.34,98.53 J7.12
  BOTTOM w0.152: v1(56.32,76.45) 56.02,76.45 R73.1
PWM7_IR_M0: length 189.5
  TOP w0.152: R110.1 v1(160.02,96.14) ; v2(81.64,17.69) J2.70
  BOTTOM w0.152: v1(160.02,96.14) 160.81,95.35 169.06,95.35 169.77,94.64 169.77,88.09 170.54,87.32 170.54,72.44 171.78,71.2 171.78,31.8 170.09,30.11 163.54,30.11 163.19,29.77 163.19,17.96 162.64,17.4 155.86,17.4 155.55,17.09 155.55,11.36 155.25,11.06 91.06,11.06 87.5,14.62 85.34,14.62 84.45,15.51 84.45,17.92 84.2,18.18 82.13,18.18 v2(81.64,17.69)
PWR_ON: length 46.9
  TOP w0.152: J1.28 47.67,17.24 48.39,16.52 48.39,14.16 45.93,11.71 33.53,11.71 33.22,12.01 33.22,16.07 32.58,16.71 28.79,16.71 28.01,17.48 v1(23.75,17.48) ; R19.2 v1(13.33,16.64)
  BOTTOM w0.152: v1(23.75,17.48) 14.17,17.48 v1(13.33,16.64)
RECOVERY: length 6
  TOP w0.152: D3.2 22.11,12.15 SW2.2 ; D3.2 R2.1 ; D3.2 C5.1
RECOVERY_KEY: length 81.8
  TOP w0.152: R2.2 v1(23.75,15.89) ; J3.50 52.07,67.32 v2(51.67,66.92)
  ART03 w0.152: v2(51.67,66.92) 51.27,67.32 50.72,67.32 50.44,67.6 50.44,67.96 50.23,68.18 40.22,68.18 39.01,66.97 35.81,66.97 35.43,66.59 35.43,64.15 v1(34.67,63.39)
  BOTTOM w0.152: v1(34.67,63.39) 34.04,62.75 34.04,58.31 34.67,57.67 34.67,46.37 35.43,45.61 35.43,18.91 33.53,17.01 24.87,17.01 v1(23.75,15.89)
RESETN: length 39.5
  TOP w0.152: R5.2 20.69,17.53 21.08,17.92 28.19,17.92 28.97,17.14 32.71,17.14 33.63,16.22 33.63,12.41 33.93,12.11 45.82,12.11 48.01,14.29 48.01,16.4 47.27,17.13 J1.26
ROUT1: length 40.1
  TOP w0.203: U16.11 20.45,72.27 v1(20.43,72.26)
  ART03 w0.203: v1(35.59,90.45) 35.16,90.87 21.66,90.87 21.16,90.36 21.16,85.94 21.46,85.64 22.81,85.64 24.21,84.24 24.21,80.96 23.8,80.56 21.59,80.56 20.85,79.82 20.85,72.68 v1(20.43,72.26)
  BOTTOM w0.203: v1(35.59,90.45) 35.34,90.69 C287.1
ROUT2: length 29.7
  TOP w0.203: U16.14 21.8,72.45 21.99,72.26 22.55,72.26 22.87,71.95 22.87,68.11 23.4,67.58 v1(26.16,67.58) ; C308.1 v1(38.99,67.97)
  ART03 w0.203: v1(26.16,67.58) 27.91,67.58 28.19,67.3 28.19,64.12 28.4,63.92 34.16,63.92 34.9,64.66 34.9,67.02 35.31,67.43 38.45,67.43 v1(38.99,67.97)
RS232_3V3: length 3.6
  TOP w0.305: U38.16 129.97,21.21 v1(129.96,21.21)
  BOTTOM w0.305: v1(129.96,21.21) 130.1,21.34 C244.1 L24.1
RS232_R1IN: length 10
  TOP w0.152: U38.13 133.77,19.56 133.15,18.94 133.15,14.95 133.83,14.27 J27.4
RS232_R1OUT: length 37.3
  TOP w0.152: U38.12 v1(135.05,21.21)
  BOTTOM w0.152: v1(135.05,21.21) 135.05,22.82 134.74,23.13 116.13,23.13 114.99,24.28 114.99,33.75 114.68,34.05 112.65,34.05 J30.1
RS232_R2IN: length 10
  TOP w0.152: U38.8 v1(138.85,15.5)
  BOTTOM w0.152: J27.1 145.26,15.02 144.77,15.5 v1(138.85,15.5)
RS232_R2OUT: length 50.6
  TOP w0.152: U38.9 v1(138.85,21.21)
  BOTTOM w0.152: v1(138.85,21.21) 138.85,24.35 138.54,24.65 117.32,24.65 117.02,24.96 117.02,36.08 116,37.1 106.93,37.1 J31.1
RS232_T1IN: length 36.9
  TOP w0.152: U38.11 v1(136.31,21.21)
  BOTTOM w0.152: J30.2 115.19,35.32 115.75,34.76 115.75,24.23 116.34,23.64 136,23.64 136.31,23.33 v1(136.31,21.21)
RS232_T1OUT: length 14.2
  TOP w0.152: v1(131.65,14.85) 131.9,15.1 131.9,20.12 132.51,20.73 U38.14
  BOTTOM w0.152: J27.6 127.65,14.5 131.3,14.5 v1(131.65,14.85)
RS232_T2IN: length 46.2
  TOP w0.152: U38.10 v1(137.59,21.21)
  BOTTOM w0.152: v1(137.59,21.21) 137.59,23.84 137.28,24.14 116.69,24.14 116.38,24.45 116.38,35.8 115.6,36.59 108.97,36.59 J31.2
RS232_T2OUT: length 3.9
  TOP w0.152: U38.7 137.59,13.1 J27.3
RS485_1_3V3: length 5.6
  TOP w0.305: U36.8 146.56,26.33 v1(146.25,26.63)
  BOTTOM w0.305: D58.2 145.64,25.4 146.25,26.01 v1(146.25,26.63) 146.56,26.94 C242.1 145.83,27.44 L22.2
RS485_1_A: length 60.8
  TOP w0.203: U36.6 144.02,26.49 144.42,26.89 144.42,27.47 144.03,27.86 141.52,27.86 R288.2 ; R288.2 140.91,27.88 140.34,27.88 140.02,27.56 140.02,11.57 139.11,10.66 129.07,10.66 128.83,10.9 128.37,11.35 128.37,17.19 128.14,17.41 127.66,17.41 DN2.1 126.37,16.59 124.1,14.32 124.1,10.91 123.46,10.26 119.56,10.26 118.89,10.92 118.89,12.74 118.58,13.05 J22.2 ; R288.2 R287.1
RS485_1_B: length 62.1
  TOP w0.203: R288.1 140.95,28.29 140.17,28.29 139.61,27.72 139.61,11.73 138.94,11.06 129.24,11.06 128.78,11.52 128.78,17.35 128.31,17.82 127.51,17.82 DN2.2 126.11,17.77 126.11,16.91 123.7,14.49 123.7,11.07 123.29,10.67 119.72,10.67 119.3,11.09 119.3,12.69 119.65,13.05 J22.1 ; R288.1 141.53,28.26 144.2,28.26 144.83,27.64 144.83,26.93 145.29,26.47 U36.7 ; R288.1 R292.1
RS485_1_DIR: length 111.3
  TOP w0.152: v1(144.02,31.75) 144.02,33.4 143.7,33.72 143.7,36.67 v1(142.71,37.66) ; v2(78.84,65.92) 78.44,66.32 J4.54 ; U36.3 144.02,29.43 144.36,29.08 144.94,29.08 145.29,29.43 U36.2
  TOP w0.173: v1(144.02,31.75) U36.3
  ART03 w0.152: v1(76.78,48.63) 77.54,48.63 77.93,49.02 79.24,49.02 79.65,48.61 80.34,48.61 80.59,48.35 84.18,48.35 85.28,49.45 115.56,49.45 116.2,48.81 142.41,48.81 142.71,48.5 v1(142.71,37.66)
  ART04 w0.152: v1(76.78,48.63) 78.42,50.27 78.42,65.5 v2(78.84,65.92)
  BOTTOM w0.173: v1(144.02,31.75) 143.98,31.79 R289.1
RS485_1_RX: length 39.7
  TOP w0.173: U36.1 v1(146.56,31.75)
  ART03 w0.152: J30.5 112.8,31.66 114.35,31.66 114.89,32.2 v1(117.59,32.2)
  BOTTOM w0.173: v1(117.59,32.2) 118.69,31.1 131.42,31.1 133.65,33.34 138.66,33.34 139.36,32.64 142.48,32.64 143.82,31.31 146.12,31.31 v1(146.56,31.75)
RS485_1_TX: length 32.1
  TOP w0.152: U36.4 v1(142.75,31.75)
  ART03 w0.152: J30.6 114.88,31.2 v1(117.59,31.2)
  BOTTOM w0.173: v1(117.59,31.2) 118.15,30.65 131.72,30.65 133.88,32.81 138.53,32.81 139.08,32.26 142.24,32.26 v1(142.75,31.75)
RS485_2_3V3: length 6.1
  TOP w0.305: U19.8 v1(138.81,26.67)
  BOTTOM w0.254: D60.2 138.43,25.53 138.81,25.91 v1(138.81,26.67) C243.1 137.95,27.44 L23.2
RS485_2_A: length 45.5
  TOP w0.203: R294.2 133.26,27.78 132.76,27.78 132.43,27.45 132.43,24.43 132.08,24.09 131.84,23.85 129.31,23.85 128.91,23.44 128.91,22.25 128.26,21.6 127.53,21.6 DN1.1 126.7,20.91 121.96,16.17 116.42,16.17 115.82,15.57 115.82,11 115.07,10.25 114.74,10.25 111.96,10.25 111.4,10.8 111.4,12.74 111.08,13.05 J22.4 ; R294.2 133.8,27.89 136.3,27.89 136.7,27.48 136.7,26.92 136.27,26.49 U19.6 ; R294.2 R293.1
RS485_2_B: length 46.8
  TOP w0.203: J22.3 112.21,13.05 111.81,12.64 111.81,10.97 112.13,10.65 114.91,10.65 115.42,11.16 115.42,15.74 116.26,16.58 121.79,16.58 125.98,20.77 125.98,21.96 DN1.2 127.64,22.01 128.09,22.01 128.5,22.42 128.5,23.61 129.14,24.26 131.68,24.26 132.02,24.6 132.02,27.62 132.59,28.19 133.1,28.19 R294.1 ; R294.1 133.75,28.29 136.46,28.29 137.11,27.65 137.11,26.9 137.54,26.47 U19.7 ; R294.1 R296.1
RS485_2_DIR: length 121.7
  TOP w0.152: U19.2 137.54,29.43 137.2,29.08 136.62,29.08 136.27,29.43 U19.3 v1(136.27,31.76) ; J4.56 v2(78.84,67.76)
  ART03 w0.152: v1(77.62,32.6) 101.07,32.6 102.16,31.51 108.31,31.51 110.72,29.1 117.49,29.1 v1(117.59,29.2)
  BOTTOM w0.152: R295.1 135.85,31.35 v1(136.27,31.76) ; v1(77.62,32.6) 77.6,32.58 74.63,32.58 74.32,32.88 74.32,33.85 74.02,34.15 69.37,34.15 69.06,34.46 69.06,42.31 69.52,42.76 75.79,42.76 76.3,43.27 76.3,54.14 75.79,54.65 75.79,64.91 76.1,65.22 78.94,65.22 79.25,65.52 79.25,67.36 78.86,67.76 v2(78.84,67.76)
  BOTTOM w0.173: v1(117.59,29.2) 117.96,29.57 132.82,29.57 135.02,31.76 v1(136.27,31.76)
RS485_2_RX: length 39.1
  TOP w0.152: U19.1 v1(138.81,31.75)
  ART03 w0.152: v1(117.59,30.2) 117.72,30.2 118.16,29.76 118.16,28.87 118.01,28.72 106.68,28.72 J31.5
  BOTTOM w0.173: v1(138.81,31.75) 138.24,32.32 134.82,32.32 132.61,30.11 117.68,30.11 v1(117.59,30.2)
RS485_2_TX: length 47.9
  TOP w0.152: v1(117.59,35.44) 118.11,34.92 118.11,32.53 118.75,31.89 129.16,31.89 129.79,32.53 134.7,32.53 135,32.22 U19.4
  BOTTOM w0.152: J31.6 106.43,31.51 106.43,33.54 105.92,34.05 104.27,34.05 103.89,34.43 103.89,37.3 104.19,37.61 117.29,37.61 117.59,37.3 v1(117.59,35.44)
RST: length 7
  TOP w0.152: R5.1 C15.1 D4.2 18.41,11.82 18.13,11.54 SW3.2
RTC_32K_IN: length 59.9
  TOP w0.152: v2(77.64,17.69) J2.50
  ART03 w0.152: v1(77.64,33.69) 78.33,34.38 102.22,34.38 103.97,36.13 115.9,36.13 v1(117.59,34.44)
  ART04 w0.152: v1(77.64,33.69) 78.08,33.25 78.08,29.05 77.64,28.61 v2(77.64,17.69)
  BOTTOM w0.152: R277.2 v1(117.59,34.44)
RTC_INT: length 66
  TOP w0.152: v2(76.84,16.85) 77.24,17.25 J2.48 ; U35.3 v1(120.47,33.68)
  ART03 w0.152: v1(120.47,33.68) 120.47,33.61 119.86,33.01 116.99,33.01 116.23,33.77 103.12,33.77 102.48,33.13 76.77,33.13 v1(76.28,33.62)
  ART04 w0.152: v2(76.84,16.85) 76.28,17.42 v1(76.28,33.62)
  BOTTOM w0.152: R3.2 120.4,33.75 v1(120.47,33.68)
S0: length 2.6
  TOP w0.152: v1(115.44,45.1) 115.44,44.78 115.14,44.48 U26.2
  BOTTOM w0.152: R226.2 115.32,44.98 v1(115.44,45.1)
S1: length 2
  TOP w0.152: U26.3 v1(112.93,45.13)
  BOTTOM w0.152: R225.2 113.07,44.98 v1(112.93,45.13)
S2: length 2.8
  TOP w0.152: R233.1 115.78,45.78 U26.4
SARADC_IN0_BOOT: length 78.5
  TOP w0.152: J3.52 v2(52.47,67.76) ; R1.2 v1(25.26,15.88)
  ART03 w0.152: v1(37.08,65.39) 39.9,65.39 40.54,66.03 51.51,66.03 52.05,66.57 52.05,67.34 v2(52.47,67.76)
  BOTTOM w0.152: v1(37.08,65.39) 35.41,63.71 35.41,63.34 34.92,62.85 34.92,58.97 35.31,58.59 35.31,46.88 35.86,46.32 35.86,18.58 35.53,18.25 35.53,17.31 34.65,16.42 25.81,16.42 v1(25.26,15.88)
SARADC_IN3: length 16.1
  TOP w0.152: J3.48 51.67,67.56 51.28,67.17 51.28,66.03 51.05,65.8 42.21,65.8 41.86,65.45 39.91,65.45 R337.1 R336.2
SARADC_IN5: length 85.1
  TOP w0.152: J3.44 v2(50.87,67.76)
  ART03 w0.152: v1(37.08,62.39) 38,62.39 38.3,62.69 38.3,64.56 38.61,64.86 40.11,64.86 40.72,65.47 51.61,65.47 52.86,66.72 52.86,67.99 52.55,68.29 51.41,68.29 v2(50.87,67.76)
  BOTTOM w0.152: R338.1 52.59,15.81 52.28,16.12 40.89,16.12 40.61,16.4 38.07,16.4 37.57,16.91 37.57,47.26 37.08,47.74 v1(37.08,62.39)
SARADC_IN6: length 81.1
  TOP w0.152: v2(50.07,66.92) 50.47,67.32 J3.42
  ART03 w0.152: v1(37.08,63.39) 37.56,63.86 37.56,64.66 37.34,64.88 36.8,64.88 36.5,65.18 36.5,65.62 36.8,65.93 39.62,65.93 40.23,66.54 49.69,66.54 v2(50.07,66.92)
  BOTTOM w0.152: v1(37.08,63.39) 36.58,62.88 36.58,47.44 37.03,46.98 37.03,15.74 37.49,15.28 40.74,15.28 40.97,15.51 49.92,15.51 R339.1
SARADC_IN7: length 80.8
  TOP w0.152: J3.40 v2(50.07,67.76)
  ART03 w0.152: v2(50.07,67.76) 49.67,67.35 43.28,67.35 42.98,67.05 39.88,67.05 39.29,66.46 36.25,66.46 35.94,66.16 35.94,64.69 36.25,64.39 v1(37.08,64.39)
  BOTTOM w0.152: R340.1 41.05,14.87 40.51,14.34 37.16,14.34 36.5,15 36.5,46.55 35.99,47.06 35.99,63.3 v1(37.08,64.39)
SATA30_0_RXN: length 4.1
  TOP w0.165: C297.1 67.58,16.12 67.58,16.84 67.91,17.17 68.45,17.17 68.79,17.5 68.79,17.9 68.84,17.95 J2.6
SATA30_0_RXP: length 4.1
  TOP w0.165: C298.1 67.29,16.12 67.29,16.96 67.79,17.46 68.33,17.46 68.49,17.62 68.49,17.9 68.44,17.95 J2.4
SATA30_0_TXN: length 3.3
  TOP w0.165: C296.1 69.59,16.15 69.59,17.9 69.64,17.95 J2.10
SATA30_0_TXP: length 3.2
  TOP w0.165: J2.8 69.24,17.95 69.29,17.9 69.29,16.09 C295.1
SATA_5V0: length 47.1
  TOP w0.173: C291.1 v1(26.66,34.76)
  TOP w0.762: J38.1 59.74,9.57 31.69,9.57 30.81,10.45 30.81,14.65 v1(30.57,14.89)
  ART03 w0.152: v1(26.66,34.76) v1(26.66,33.76)
  BOTTOM w0.152: v1(26.66,33.76) 26.54,33.64 19.3,33.64 19.04,33.91 R316.2 C290.2
  vias: v1(27.66,33.76) v1(28.66,34.76) v1(28.66,33.76) v1(29.57,15.89) v1(29.57,14.89) v1(30.57,15.89) v1(31.57,15.89) v1(31.57,14.89)
SATA_12V: length 40.8
  BOTTOM w0.762: 29.72,8.71 67.81,8.71 68.83,9.73 J38.4
  vias: v1(11.77,9.49) v1(11.77,8.49) v1(12.77,9.49) v1(12.77,8.49) v1(13.77,9.49) v1(13.77,8.49)
SATA_PWR_EN: length 110.2
  TOP w0.152: J2.69 81.64,22.98 82.04,23.38 v2(82.04,27.12) ; v1(12.34,28.2) 12.19,28.05 R320.1
  ART03 w0.152: v2(82.04,27.12) 81.69,27.47 58.62,27.47 56.54,29.56 33.44,29.56 v1(33,29.12)
  BOTTOM w0.152: v1(33,29.12) 34.21,29.12 34.95,28.39 34.95,19.12 33.43,17.59 26.85,17.59 25.88,18.56 14.66,18.56 14.2,19.01 14.2,23.44 13.46,24.18 12.69,24.18 12.34,24.53 v1(12.34,28.2) 12.78,28.64 12.78,32.87 13,33.1 15.67,33.1 16.01,33.43 R318.2
SATA_RXN: length 19.8
  TOP w0.165: C297.2 67.58,14.39 67.58,13.84 v1(67.82,13.61)
  BOTTOM w0.165: J39.5 78.78,11.24 78.78,13.39 D86.2 79.13,14.19 78.76,14.56 78.76,15.15 78.26,15.65 77.17,15.65 74.26,12.74 67.72,12.74 67.56,12.91 67.56,13.34 v1(67.82,13.61)
SATA_RXP: length 19.8
  TOP w0.165: v1(67,13.61) 67.29,13.89 67.29,14.39 C298.2
  BOTTOM w0.165: J39.6 78.49,11.24 78.49,13.34 D85.2 78.1,14.19 78.47,14.56 78.47,15.03 78.14,15.36 77.29,15.36 74.38,12.45 67.6,12.45 67.27,12.78 67.27,13.34 v1(67,13.61)
SATA_TXN: length 23.6
  TOP w0.165: v1(80.73,14.73) 80.99,14.99 81.36,14.99 81.56,14.79 81.56,13.96 81.19,13.59 80.78,13.59 arc(80.65,13.64) 80.6,13.76 arc(80.55,13.88) 80.43,13.93 80.12,13.93 arc(79.99,13.88) 79.94,13.76 arc(79.89,13.64) 79.77,13.59 79.45,13.59 arc(79.33,13.64) 79.28,13.76 arc(79.23,13.88) 79.11,13.93 78.79,13.93 arc(78.67,13.88) 78.62,13.76 arc(78.57,13.64) 78.45,13.59 78.13,13.59 arc(78.01,13.64) 77.96,13.76 arc(77.91,13.88) 77.79,13.93 77.47,13.93 arc(77.35,13.88) 77.3,13.76 arc(77.25,13.64) 77.13,13.59 76.81,13.59 arc(76.69,13.64) 76.64,13.76 arc(76.59,13.88) 76.47,13.93 76.15,13.93 arc(76.03,13.88) 75.98,13.76 arc(75.93,13.64) 75.81,13.59 75.49,13.59 arc(75.37,13.64) 75.32,13.76 arc(75.27,13.88) 75.15,13.93 74.83,13.93 arc(74.71,13.88) 74.66,13.76 arc(74.61,13.64) 74.49,13.59 69.78,13.59 69.62,13.76 69.62,14.39 C296.2
  BOTTOM w0.165: J39.3 82.3,11.24 82.3,12.1 82.53,12.33 82.53,13.36 D87.2 82.53,14.1 82.53,14.49 82.04,14.99 80.99,14.99 v1(80.73,14.73)
SATA_TXP: length 23.6
  TOP w0.165: C295.2 69.32,14.39 69.32,13.64 69.66,13.3 81.31,13.3 81.85,13.84 81.85,14.91 81.48,15.28 80.99,15.28 v1(80.73,15.54)
  BOTTOM w0.165: J39.2 82.59,11.24 82.59,11.98 82.82,12.21 82.82,13.36 D88.2 82.82,14.1 82.82,14.61 82.16,15.28 80.99,15.28 v1(80.73,15.54)
SD_CD: length 5.8
  TOP w0.173: J24.9 155.89,16.09 D16.2 155.19,15.38 153.92,15.38 R283.2
SD_CLK: length 6
  TOP w0.173: R280.2 153.92,19.19 155.19,19.19 D19.2 156.48,20.49 J24.5
SD_CMD: length 5.8
  TOP w0.173: R279.2 153.89,21.88 155.21,21.88 D20.2 156.01,22.69 J24.3
SD_DAT0: length 5.9
  TOP w0.173: J24.7 156.09,18.29 D18.2 155.19,17.92 153.92,17.92 R281.2
SD_DAT1: length 5.8
  TOP w0.173: J24.8 155.92,17.19 D17.2 155.19,16.65 153.92,16.65 R282.2
SD_DAT2: length 5.8
  TOP w0.173: J24.1 155.97,24.89 D22.2 155.21,24.42 153.89,24.42 R275.2
SD_DAT3: length 5.8
  TOP w0.173: J24.2 155.84,23.79 D21.2 155.19,23.13 153.92,23.13 R278.2
SDMMC_CLK: length 116.4
  TOP w0.173: R280.1 v1(151.51,19.83) ; J4.77 83.24,63.92 v2(82.84,63.52)
  ART04 w0.16: v2(82.84,63.52) 82.84,62.89 82.61,62.66 82.61,55.6 86.97,51.25 96.79,51.25 97.28,50.77 104.67,50.77 105.16,51.25 113.26,51.25 114.58,52.57 142.17,52.57 153.39,41.35 153.39,28.17 153.58,27.99 154.45,27.99 154.64,27.8 154.64,23.44 154.1,22.91 153.57,22.91 152.83,22.17 150.13,22.17 149.87,21.91 149.87,20.76 150.18,20.45 151.19,20.45 151.51,20.13 v1(151.51,19.83)
SDMMC_CMD: length 117
  TOP w0.173: R279.1 150.86,22.49 150.51,22.15 v1(150.51,21.22) ; J4.79 v2(83.64,64.36)
  ART04 w0.16: v1(150.51,21.22) 150.9,21.61 154.81,21.61 155.17,21.97 155.17,28.54 154.98,28.73 154.2,28.73 153.97,28.95 153.97,29.24 154.16,29.43 154.73,29.43 154.91,29.62 154.91,29.88 154.73,30.07 154.16,30.07 153.97,30.26 153.97,41.5 142.29,53.18 114.45,53.18 113.17,51.9 87.04,51.9 83.23,55.72 83.23,63.94 v2(83.64,64.36)
SDMMC_D0: length 117.3
  TOP w0.173: v2(81.24,63.52) 81.64,63.92 J4.69 ; v1(149.86,18.56) R281.1
  ART04 w0.16: v2(81.24,63.52) 81.49,63.27 81.49,55.14 86.41,50.22 96.37,50.22 96.85,49.73 105.46,49.73 105.95,50.22 113.8,50.22 114.96,51.37 138.38,51.37 139.01,50.74 142.37,50.74 152.28,40.83 152.28,23.57 151.96,23.25 148.93,23.25 148.61,22.92 148.61,18.88 148.93,18.56 v1(149.86,18.56)
SDMMC_D1: length 117.7
  TOP w0.173: J4.71 v2(82.04,64.36) ; R282.1 v1(151.51,17.29)
  ART04 w0.16: v2(82.04,64.36) 82.43,63.97 82.43,63.14 82.1,62.81 82.1,55.39 86.75,50.73 96.58,50.73 97.06,50.25 105.16,50.25 105.64,50.73 113.48,50.73 114.76,52.01 142,52.01 152.86,41.15 152.86,23.06 152.53,22.73 149.67,22.73 149.35,22.41 149.35,19.62 149.67,19.3 151.19,19.3 151.51,18.98 v1(151.51,17.29)
SDMMC_D2: length 117.8
  TOP w0.173: R275.1 v1(151.54,25.03) ; v2(82.04,63.52) 82.44,63.92 J4.73
  ART04 w0.16: v1(151.54,25.03) 151.54,37.85 151.24,38.14 148.22,38.14 148.06,38.3 148.06,38.59 148.24,38.77 150.66,38.77 150.88,38.99 150.88,39.25 150.71,39.41 148.24,39.41 148.06,39.6 148.06,39.87 148.24,40.06 150.66,40.06 150.88,40.27 150.88,40.53 150.69,40.72 148.34,40.72 148.18,40.88 148.18,43.66 141.67,50.18 135.15,50.18 134.75,50.59 115.09,50.59 114.11,49.61 106.07,49.61 105.68,49.22 96.34,49.22 95.94,49.61 86.29,49.61 80.98,54.93 80.98,62.83 80.87,62.94 80.87,63.67 81.09,63.89 81.67,63.89 v2(82.04,63.52)
